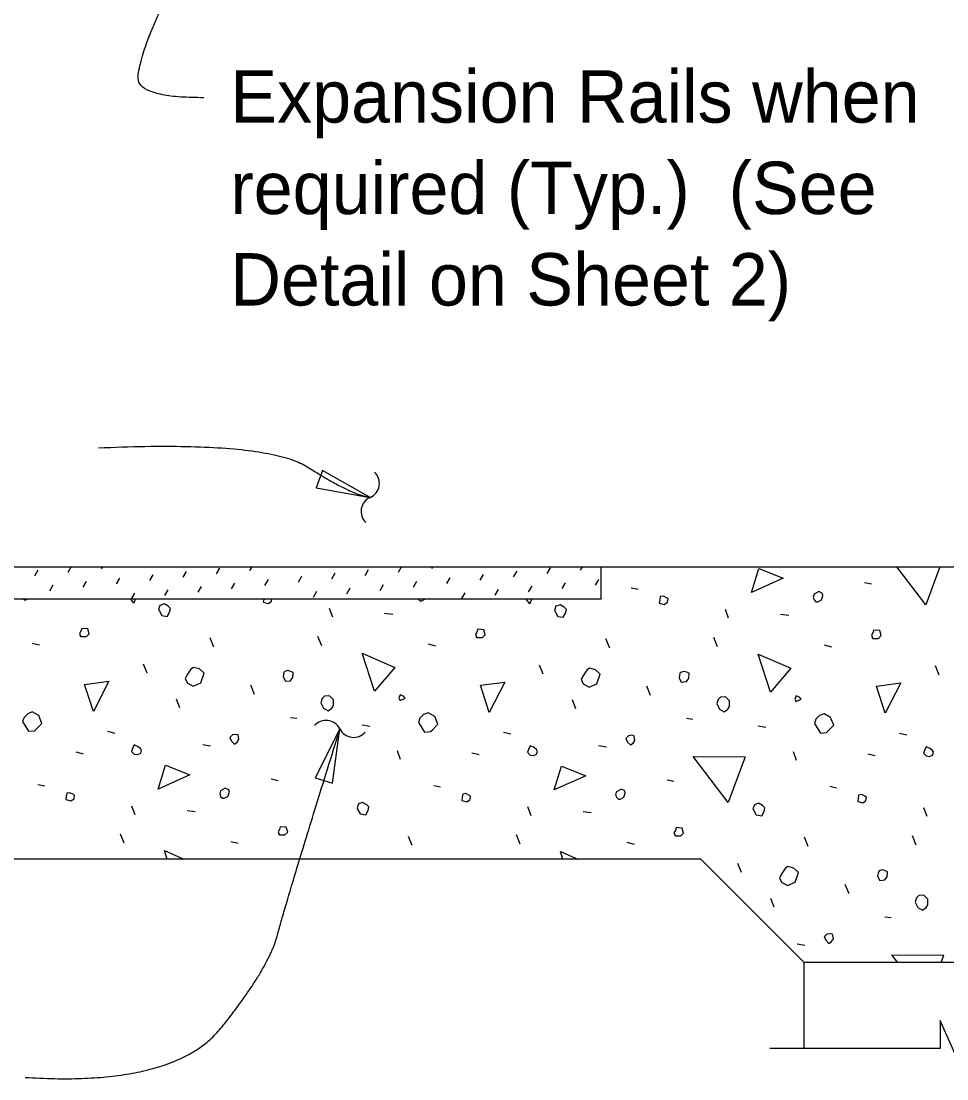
# Model space of a CAD drawing. Extents: x 110341.7 to 110413.5, y 110387.3 to 110417.8.
# Drawn here: x 110360.284 to 110363.847, y 110401.872 to 110405.944 of the extents above; entities that cross this region are included whole.
import ezdxf

# ---------------------------------------------------------------- set-up
doc = ezdxf.new("R2010")
doc.units = 0
for name, color, linetype in [('Border', 7, 'Continuous'), ('Patterning', 7, 'Continuous'), ('PlotBorder_dp', 7, 'Continuous')]:
    doc.layers.add(name, color=color, linetype=linetype)

msp = doc.modelspace()

# ---------------------------------------------------------------- linework, layer by layer
at = {"layer": 'Border'}
for points in [[(110361.6272, 110404.1098), (110361.4436, 110404.2143), (110361.4194, 110404.148)], [(110361.5112, 110403.2194), (110361.4155, 110403.0312), (110361.4828, 110403.0101)]]:
    msp.add_lwpolyline(points, close=True, dxfattribs=at)
msp.add_lwpolyline([(110364.6174, 110401.9889), (110363.9204, 110401.9889), (110363.9204, 110401.8726), (110363.821, 110402.0976), (110363.821, 110401.9889), (110363.1658, 110401.9889)], dxfattribs=at)
for centre, start, end in [((110361.6031, 110404.165), 294.1466, 45.8738), ((110361.6519, 110404.0562), 114.1466, 225.8738), ((110361.4573, 110403.1927), 26.8413, 138.5686), ((110361.5637, 110403.2465), 206.8413, 318.5686)]:
    msp.add_arc(centre, 0.0596, start, end, dxfattribs=at)
for points in [[(110360.9877, 110405.649), (110360.7244, 110405.649), (110360.7442, 110405.8149), (110360.8614, 110406.0797), (110360.932, 110406.1998), (110360.999, 110406.1998), (110360.999, 110406.1433), (110360.9285, 110406.0868), (110360.7909, 110406.0268)], [(110360.5818, 110404.3015), (110361.2295, 110404.3299), (110361.5509, 110404.1217), (110361.6275, 110404.1106)], [(110360.2997, 110401.8779), (110360.8727, 110401.8414), (110361.2376, 110402.2981), (110361.3039, 110402.5554), (110361.5112, 110403.2194)]]:
    msp.add_open_spline(points, degree=2, dxfattribs=at)
at = {"layer": 'Patterning'}
for p, q in [((110360.3363, 110403.8093), (110360.3493, 110403.8317)), ((110360.4648, 110403.8223), (110360.4771, 110403.8435)), ((110360.5932, 110403.8352), (110360.598, 110403.8435)), ((110360.9079, 110403.8034), (110360.9209, 110403.8258)), ((110361.0364, 110403.8164), (110361.0493, 110403.8388)), ((110361.1648, 110403.8293), (110361.173, 110403.8435)), ((110361.2933, 110403.8423), (110361.294, 110403.8435)), ((110361.4795, 110403.7975), (110361.4924, 110403.8199)), ((110361.6079, 110403.8105), (110361.6209, 110403.8329)), ((110361.7364, 110403.8234), (110361.748, 110403.8435)), ((110361.8648, 110403.8364), (110361.869, 110403.8435)), ((110362.1795, 110403.8046), (110362.1925, 110403.827)), ((110362.308, 110403.8175), (110362.3209, 110403.8399)), ((110362.4364, 110403.8305), (110362.444, 110403.8435)), ((110360.5225, 110403.7645), (110360.5355, 110403.7869)), ((110360.651, 110403.7775), (110360.6639, 110403.7999)), ((110360.7794, 110403.7904), (110360.7924, 110403.8128)), ((110361.0941, 110403.7586), (110361.1071, 110403.781)), ((110361.2226, 110403.7716), (110361.2355, 110403.794)), ((110361.351, 110403.7845), (110361.364, 110403.8069)), ((110361.7941, 110403.7657), (110361.8071, 110403.7881)), ((110361.9226, 110403.7787), (110361.9356, 110403.801)), ((110362.0511, 110403.7916), (110362.064, 110403.814)), ((110362.3657, 110403.7598), (110362.3787, 110403.7822)), ((110362.4942, 110403.7728), (110362.5071, 110403.7952)), ((110363.5302, 110403.7834), (110363.5567, 110403.7781)), ((110360.3941, 110403.7515), (110360.407, 110403.7739)), ((110360.7087, 110403.7197), (110360.7217, 110403.7421)), ((110360.8372, 110403.7327), (110360.8501, 110403.7551)), ((110360.9656, 110403.7457), (110360.9786, 110403.768)), ((110361.4088, 110403.7268), (110361.4217, 110403.7492)), ((110361.5372, 110403.7398), (110361.5502, 110403.7622)), ((110361.6657, 110403.7527), (110361.6786, 110403.7751)), ((110361.9803, 110403.7209), (110361.9933, 110403.7433)), ((110362.1088, 110403.7339), (110362.1218, 110403.7563)), ((110362.2373, 110403.7468), (110362.2502, 110403.7692)), ((110362.6322, 110403.7622), (110362.6587, 110403.7569)), ((110361.4831, 110403.6491), (110361.4707, 110403.6827)), ((110361.6829, 110403.665), (110361.7147, 110403.6614)), ((110363.0069, 110403.6455), (110362.9945, 110403.6791)), ((110363.2067, 110403.6614), (110363.2385, 110403.6579)), ((110360.327, 110403.5501), (110360.3553, 110403.543)), ((110361.0253, 110403.5342), (110361.0111, 110403.5695)), ((110361.4407, 110403.5395), (110361.4265, 110403.5748)), ((110361.8508, 110403.5465), (110361.8791, 110403.5395)), ((110362.5491, 110403.5306), (110362.5349, 110403.566)), ((110362.9645, 110403.5359), (110362.9504, 110403.5713)), ((110363.3746, 110403.543), (110363.4029, 110403.5359)), ((110360.7689, 110403.4334), (110360.7548, 110403.4688)), ((110362.2927, 110403.4299), (110362.2786, 110403.4652)), ((110363.8166, 110403.4263), (110363.8024, 110403.4617)), ((110361.1826, 110403.3521), (110361.1684, 110403.3874)), ((110362.7064, 110403.3485), (110362.6923, 110403.3839)), ((110360.8944, 110403.3008), (110360.8821, 110403.3344)), ((110362.4183, 110403.2973), (110362.4059, 110403.3309)), ((110361.3205, 110403.2637), (110361.3452, 110403.2602)), ((110362.8443, 110403.2602), (110362.869, 110403.2566)), ((110360.6169, 110403.2107), (110360.6452, 110403.2036)), ((110361.5962, 110403.2354), (110361.6263, 110403.2301)), ((110363.1201, 110403.2319), (110363.1501, 110403.2266)), ((110362.1407, 110403.2071), (110362.169, 110403.2001)), ((110363.6645, 110403.2036), (110363.6928, 110403.1965)), ((110360.4949, 110403.1311), (110360.5232, 110403.124)), ((110360.9828, 110403.1594), (110361.0129, 110403.1541)), ((110361.7447, 110403.1011), (110361.7324, 110403.1346)), ((110362.0187, 110403.1276), (110362.047, 110403.1205)), ((110362.5066, 110403.1559), (110362.5367, 110403.1506)), ((110363.2686, 110403.0975), (110363.2562, 110403.1311)), ((110363.5426, 110403.124), (110363.5708, 110403.117)), ((110360.3482, 110403.0056), (110360.3747, 110403.0003)), ((110361.2462, 110403.0268), (110361.2727, 110403.0215)), ((110362.77, 110403.0233), (110362.7966, 110403.018)), ((110361.872, 110403.0021), (110361.8985, 110402.9968)), ((110363.3958, 110402.9985), (110363.4223, 110402.9932)), ((110360.723, 110402.8889), (110360.7106, 110402.9225)), ((110360.9227, 110402.9048), (110360.9545, 110402.9013)), ((110362.2468, 110402.8854), (110362.2344, 110402.919)), ((110362.4465, 110402.9013), (110362.4784, 110402.8978)), ((110363.7706, 110402.8819), (110363.7582, 110402.9154)), ((110360.6805, 110402.7793), (110360.6664, 110402.8147)), ((110361.7889, 110402.7705), (110361.7748, 110402.8058)), ((110362.2044, 110402.7758), (110362.1902, 110402.8111)), ((110363.3127, 110402.767), (110363.2986, 110402.8023)), ((110363.7282, 110402.7723), (110363.714, 110402.8076)), ((110361.0907, 110402.7864), (110361.1189, 110402.7793)), ((110362.6145, 110402.7829), (110362.6428, 110402.7758)), ((110363.0564, 110402.6662), (110363.0423, 110402.7015)), ((110363.4701, 110402.5849), (110363.4559, 110402.6202)), ((110363.1819, 110402.5336), (110363.1696, 110402.5672)), ((110363.608, 110402.4965), (110363.6327, 110402.493)), ((110363.2703, 110402.3922), (110363.3004, 110402.3869))]:
    msp.add_line(p, q, dxfattribs=at)
for points in [[(110363.0953, 110403.7445), (110363.1236, 110403.8365), (110363.2173, 110403.7993), (110363.0953, 110403.7445)], [(110363.7653, 110403.6968), (110363.6538, 110403.8435)], [(110363.8201, 110403.8435), (110363.7653, 110403.6968)], [(110363.3428, 110403.7092), (110363.3499, 110403.7092), (110363.364, 110403.7162), (110363.3693, 110403.7322), (110363.3675, 110403.741), (110363.3534, 110403.7481), (110363.3357, 110403.7375), (110363.3322, 110403.7269), (110363.3357, 110403.7162), (110363.3428, 110403.7092)], [(110360.2929, 110403.7185), (110360.2952, 110403.7162)], [(110360.2952, 110403.7162), (110360.3022, 110403.7162), (110360.3068, 110403.7185)], [(110360.7177, 110403.7039), (110360.7065, 110403.7185)], [(110360.7231, 110403.7185), (110360.7177, 110403.7039)], [(110360.8167, 110403.6721), (110360.8255, 110403.6561), (110360.8467, 110403.6526), (110360.8555, 110403.6685), (110360.8591, 110403.6827), (110360.8502, 110403.6915), (110360.8343, 110403.7003), (110360.8184, 110403.695), (110360.8131, 110403.6791), (110360.8167, 110403.6721)], [(110361.2162, 110403.7074), (110361.2356, 110403.7021), (110361.248, 110403.7109), (110361.2491, 110403.7185)], [(110361.2178, 110403.7185), (110361.2162, 110403.7074)], [(110361.8131, 110403.7185), (110361.819, 110403.7127)], [(110361.819, 110403.7127), (110361.8261, 110403.7127), (110361.8377, 110403.7185)], [(110362.2415, 110403.7003), (110362.2276, 110403.7185)], [(110362.2483, 110403.7185), (110362.2415, 110403.7003)], [(110362.74, 110403.7039), (110362.7594, 110403.6986), (110362.7718, 110403.7074), (110362.7736, 110403.7198), (110362.77, 110403.7233), (110362.7559, 110403.7304), (110362.7435, 110403.7286), (110362.7418, 110403.7162), (110362.74, 110403.7039)], [(110362.3405, 110403.6685), (110362.3493, 110403.6526), (110362.3705, 110403.6491), (110362.3794, 110403.665), (110362.3829, 110403.6791), (110362.3741, 110403.688), (110362.3582, 110403.6968), (110362.3422, 110403.6915), (110362.3369, 110403.6756), (110362.3405, 110403.6685)], [(110360.5144, 110403.5748), (110360.5356, 110403.5748), (110360.5462, 110403.5854), (110360.5409, 110403.6049), (110360.5179, 110403.6066), (110360.5144, 110403.596), (110360.5091, 110403.5872), (110360.5144, 110403.5748), (110360.5108, 110403.5784)], [(110362.0382, 110403.5713), (110362.0594, 110403.5713), (110362.07, 110403.5819), (110362.0647, 110403.6013), (110362.0417, 110403.6031), (110362.0382, 110403.5925), (110362.0329, 110403.5837), (110362.0382, 110403.5713), (110362.0347, 110403.5748)], [(110363.562, 110403.5678), (110363.5832, 110403.5678), (110363.5938, 110403.5784), (110363.5885, 110403.5978), (110363.5655, 110403.5996), (110363.562, 110403.589), (110363.5567, 110403.5801), (110363.562, 110403.5678), (110363.5585, 110403.5713)], [(110361.644, 110403.3645), (110361.5962, 110403.5112), (110361.7218, 110403.4564), (110361.644, 110403.3645)], [(110363.1678, 110403.3609), (110363.1201, 110403.5076), (110363.2456, 110403.4528), (110363.1678, 110403.3609)], [(110360.9227, 110403.3963), (110360.9457, 110403.3839), (110360.9758, 110403.3963), (110360.9881, 110403.4334), (110360.9705, 110403.4511), (110360.9475, 110403.4564), (110360.9369, 110403.4493), (110360.9245, 110403.4299), (110360.9157, 110403.414), (110360.9227, 110403.3963)], [(110361.2922, 110403.4193), (110361.301, 110403.4034), (110361.3205, 110403.4051), (110361.3293, 110403.4175), (110361.3311, 110403.4369), (110361.3187, 110403.4422), (110361.3099, 110403.444), (110361.2993, 110403.4405), (110361.2957, 110403.4369), (110361.2922, 110403.4193)], [(110362.4465, 110403.3927), (110362.4695, 110403.3804), (110362.4996, 110403.3927), (110362.5119, 110403.4299), (110362.4943, 110403.4475), (110362.4713, 110403.4528), (110362.4607, 110403.4458), (110362.4483, 110403.4263), (110362.4395, 110403.4104), (110362.4465, 110403.3927)], [(110362.816, 110403.4157), (110362.8248, 110403.3998), (110362.8443, 110403.4016), (110362.8531, 110403.414), (110362.8549, 110403.4334), (110362.8425, 110403.4387), (110362.8337, 110403.4405), (110362.8231, 110403.4369), (110362.8195, 110403.4334), (110362.816, 110403.4157)], [(110360.5621, 110403.2867), (110360.5285, 110403.391), (110360.6222, 110403.4034), (110360.5621, 110403.2867)], [(110362.0859, 110403.2831), (110362.0523, 110403.3874), (110362.146, 110403.3998), (110362.0859, 110403.2831)], [(110363.6097, 110403.2796), (110363.5761, 110403.3839), (110363.6698, 110403.3963), (110363.6097, 110403.2796)], [(110361.4371, 110403.3203), (110361.4478, 110403.2991), (110361.4654, 110403.2884), (110361.4796, 110403.2991), (110361.4866, 110403.3097), (110361.4866, 110403.3309), (110361.4707, 110403.3468), (110361.4513, 110403.345), (110361.4424, 110403.3362), (110361.4371, 110403.3203)], [(110361.743, 110403.3291), (110361.7624, 110403.3379), (110361.7553, 110403.345), (110361.743, 110403.3503), (110361.7377, 110403.3379), (110361.743, 110403.3291)], [(110362.961, 110403.3167), (110362.9716, 110403.2955), (110362.9892, 110403.2849), (110363.0034, 110403.2955), (110363.0105, 110403.3061), (110363.0105, 110403.3273), (110362.9945, 110403.3432), (110362.9751, 110403.3415), (110362.9663, 110403.3326), (110362.961, 110403.3167)], [(110363.2668, 110403.3256), (110363.2862, 110403.3344), (110363.2792, 110403.3415), (110363.2668, 110403.3468), (110363.2615, 110403.3344), (110363.2668, 110403.3256)], [(110360.2899, 110403.2478), (110360.3128, 110403.2107), (110360.3358, 110403.2124), (110360.3447, 110403.2213), (110360.3641, 110403.2407), (110360.3517, 110403.2708), (110360.327, 110403.2849), (110360.3093, 110403.2778), (110360.2952, 110403.2637), (110360.2899, 110403.2478)], [(110361.8137, 110403.2443), (110361.8367, 110403.2071), (110361.8596, 110403.2089), (110361.8685, 110403.2177), (110361.8879, 110403.2372), (110361.8756, 110403.2672), (110361.8508, 110403.2814), (110361.8331, 110403.2743), (110361.819, 110403.2602), (110361.8137, 110403.2443)], [(110363.3375, 110403.2407), (110363.3605, 110403.2036), (110363.3835, 110403.2054), (110363.3923, 110403.2142), (110363.4117, 110403.2336), (110363.3994, 110403.2637), (110363.3746, 110403.2778), (110363.3569, 110403.2708), (110363.3428, 110403.2566), (110363.3375, 110403.2407)], [(110361.0942, 110403.1718), (110361.1048, 110403.1612), (110361.1154, 110403.1682), (110361.1225, 110403.1788), (110361.1189, 110403.1965), (110361.1101, 110403.1983), (110361.0977, 110403.1965), (110361.0871, 110403.1859), (110361.0942, 110403.1718)], [(110362.618, 110403.1682), (110362.6286, 110403.1576), (110362.6392, 110403.1647), (110362.6463, 110403.1753), (110362.6428, 110403.193), (110362.6339, 110403.1948), (110362.6215, 110403.193), (110362.6109, 110403.1824), (110362.618, 110403.1682)], [(110360.7194, 110403.1223), (110360.7318, 110403.1205), (110360.7442, 110403.1258), (110360.7477, 110403.1364), (110360.7424, 110403.1453), (110360.7318, 110403.1523), (110360.7194, 110403.1576), (110360.7124, 110403.1435), (110360.7088, 110403.1329), (110360.7194, 110403.1223)], [(110362.2432, 110403.1187), (110362.2556, 110403.117), (110362.268, 110403.1223), (110362.2715, 110403.1329), (110362.2662, 110403.1417), (110362.2556, 110403.1488), (110362.2432, 110403.1541), (110362.2362, 110403.14), (110362.2326, 110403.1293), (110362.2432, 110403.1187)], [(110363.7671, 110403.1152), (110363.7794, 110403.1134), (110363.7918, 110403.1187), (110363.7953, 110403.1293), (110363.79, 110403.1382), (110363.7794, 110403.1453), (110363.7671, 110403.1506), (110363.76, 110403.1364), (110363.7565, 110403.1258), (110363.7671, 110403.1152)], [(110363.0052, 110402.9367), (110362.8708, 110403.1134), (110363.0706, 110403.1117), (110363.0052, 110402.9367)], [(110360.8114, 110402.9879), (110360.8396, 110403.0798), (110360.9333, 110403.0427), (110360.8114, 110402.9879)], [(110362.3352, 110402.9844), (110362.3635, 110403.0763), (110362.4571, 110403.0392), (110362.3352, 110402.9844)], [(110360.456, 110402.9473), (110360.4755, 110402.942), (110360.4879, 110402.9508), (110360.4896, 110402.9632), (110360.4861, 110402.9667), (110360.4719, 110402.9738), (110360.4596, 110402.972), (110360.4578, 110402.9596), (110360.456, 110402.9473)], [(110361.0588, 110402.9526), (110361.0659, 110402.9526), (110361.0801, 110402.9596), (110361.0854, 110402.9756), (110361.0836, 110402.9844), (110361.0694, 110402.9915), (110361.0518, 110402.9809), (110361.0482, 110402.9702), (110361.0518, 110402.9596), (110361.0588, 110402.9526)], [(110361.9798, 110402.9437), (110361.9993, 110402.9384), (110362.0117, 110402.9473), (110362.0134, 110402.9596), (110362.0099, 110402.9632), (110361.9958, 110402.9702), (110361.9834, 110402.9685), (110361.9816, 110402.9561), (110361.9798, 110402.9437)], [(110362.5827, 110402.949), (110362.5897, 110402.949), (110362.6039, 110402.9561), (110362.6092, 110402.972), (110362.6074, 110402.9809), (110362.5933, 110402.9879), (110362.5756, 110402.9773), (110362.5721, 110402.9667), (110362.5756, 110402.9561), (110362.5827, 110402.949)], [(110363.5037, 110402.9402), (110363.5231, 110402.9349), (110363.5355, 110402.9437), (110363.5373, 110402.9561), (110363.5337, 110402.9596), (110363.5196, 110402.9667), (110363.5072, 110402.9649), (110363.5054, 110402.9526), (110363.5037, 110402.9402)], [(110361.5803, 110402.9084), (110361.5892, 110402.8925), (110361.6104, 110402.8889), (110361.6192, 110402.9048), (110361.6228, 110402.919), (110361.6139, 110402.9278), (110361.598, 110402.9367), (110361.5821, 110402.9314), (110361.5768, 110402.9154), (110361.5803, 110402.9084)], [(110363.1041, 110402.9048), (110363.113, 110402.8889), (110363.1342, 110402.8854), (110363.143, 110402.9013), (110363.1466, 110402.9154), (110363.1377, 110402.9243), (110363.1218, 110402.9331), (110363.1059, 110402.9278), (110363.1006, 110402.9119), (110363.1041, 110402.9048)], [(110361.278, 110402.8111), (110361.2993, 110402.8111), (110361.3099, 110402.8218), (110361.3046, 110402.8412), (110361.2816, 110402.843), (110361.278, 110402.8324), (110361.2727, 110402.8235), (110361.278, 110402.8111), (110361.2745, 110402.8147)], [(110362.8019, 110402.8076), (110362.8231, 110402.8076), (110362.8337, 110402.8182), (110362.8284, 110402.8377), (110362.8054, 110402.8394), (110362.8019, 110402.8288), (110362.7966, 110402.82), (110362.8019, 110402.8076), (110362.7983, 110402.8111)], [(110360.8467, 110402.7185), (110360.8361, 110402.751), (110360.9106, 110402.7185)], [(110362.3693, 110402.7185), (110362.3599, 110402.7475), (110362.4263, 110402.7185)], [(110363.2102, 110402.6291), (110363.2332, 110402.6167), (110363.2632, 110402.6291), (110363.2756, 110402.6662), (110363.2579, 110402.6839), (110363.235, 110402.6892), (110363.2244, 110402.6821), (110363.212, 110402.6627), (110363.2031, 110402.6467), (110363.2102, 110402.6291)], [(110363.5797, 110402.652), (110363.5885, 110402.6361), (110363.608, 110402.6379), (110363.6168, 110402.6503), (110363.6186, 110402.6697), (110363.6062, 110402.675), (110363.5974, 110402.6768), (110363.5867, 110402.6733), (110363.5832, 110402.6697), (110363.5797, 110402.652)], [(110363.7246, 110402.5531), (110363.7352, 110402.5318), (110363.7529, 110402.5212), (110363.7671, 110402.5318), (110363.7741, 110402.5424), (110363.7741, 110402.5637), (110363.7582, 110402.5796), (110363.7388, 110402.5778), (110363.7299, 110402.569), (110363.7246, 110402.5531)], [(110363.3817, 110402.4046), (110363.3923, 110402.394), (110363.4029, 110402.401), (110363.41, 110402.4116), (110363.4064, 110402.4293), (110363.3976, 110402.4311), (110363.3852, 110402.4293), (110363.3746, 110402.4187), (110363.3817, 110402.4046)], [(110363.6562, 110402.3212), (110363.6345, 110402.3498), (110363.8342, 110402.348), (110363.8242, 110402.3212)]]:
    msp.add_lwpolyline(points, dxfattribs=at)
at = {"layer": 'PlotBorder_dp'}
for p, q in [((110357.2147, 110403.8435), (110364.5166, 110403.8435)), ((110362.5166, 110403.7185), (110362.5166, 110403.8435)), ((110362.5166, 110403.7185), (110357.2147, 110403.7185)), ((110362.8993, 110402.7185), (110357.2147, 110402.7185)), ((110363.2966, 110402.3212), (110362.8993, 110402.7185)), ((110363.2966, 110402.3212), (110364.5166, 110402.3212)), ((110363.2966, 110402.3212), (110363.2966, 110401.9889))]:
    msp.add_line(p, q, dxfattribs=at)

# ---------------------------------------------------------------- texts
at = {"layer": 'Border'}
for s, p in [('Expansion Rails when ', (110361.0894, 110405.5533)), ('required (Typ.)  (See ', (110361.0894, 110405.2013)), ('Detail on Sheet 2)', (110361.0894, 110404.8493))]:
    msp.add_text(s, height=0.2016, dxfattribs=at).set_placement(p)

doc.saveas('drawing.dxf')
